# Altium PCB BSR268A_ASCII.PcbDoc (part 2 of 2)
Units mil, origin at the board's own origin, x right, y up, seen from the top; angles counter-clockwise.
Board outline 3689.1 x 2409.61 mil, 4 copper layers (Top Layer, Signal Layer 1, Signal Layer 2, Bottom Layer), stack 60.312 mil thick; 90 components, 29 nets, 160 pads, 335 vias.
Unrouted connection lines stored in the file: 5.
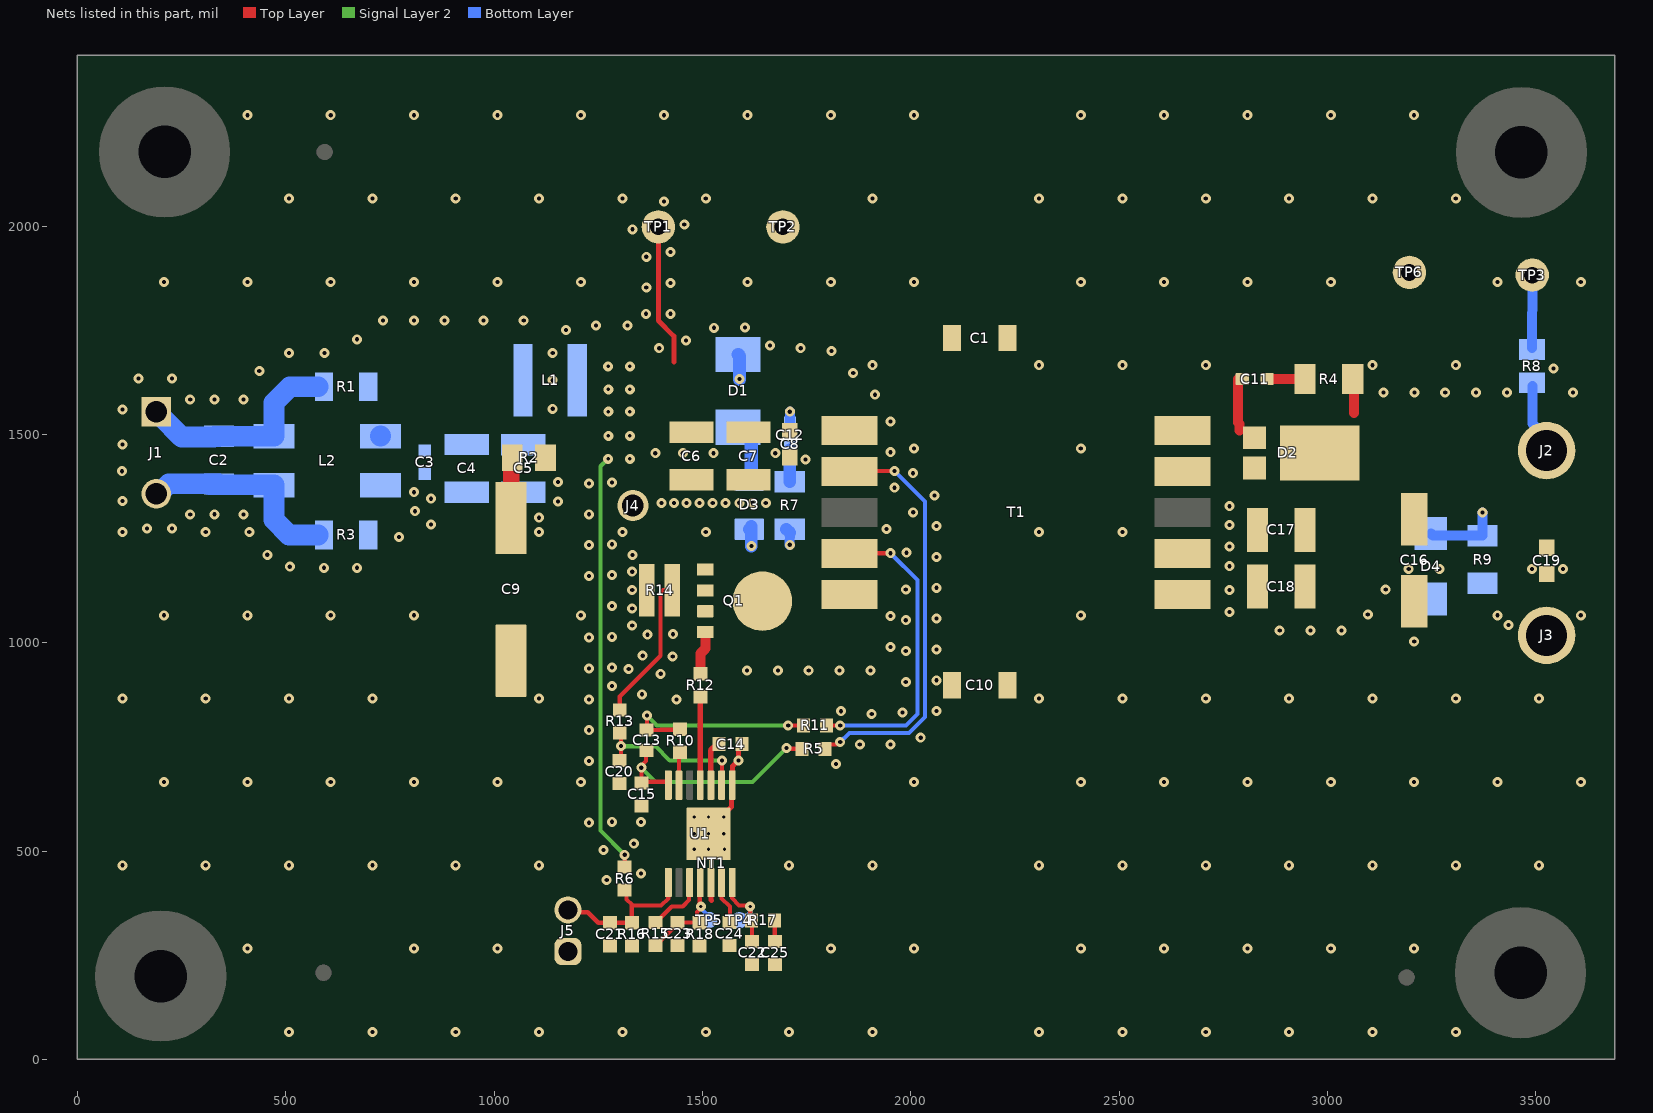
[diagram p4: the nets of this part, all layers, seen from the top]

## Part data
C1 C10: library part CMP-0008572-2, "CAP, CERM, 1000 pF, 2000 V, +/- 10%, X7R, 1206_190"
C2: library part CMP-0008881-2, "CAP, CERM, 0.1 uF, 100 V, +/- 10%, X7R, 1206"
C3 C8 C15 C19: library part CMP-0007469-4, "CAP, CERM, 0.1 uF, 100 V, +/- 10%, X7R, 0603"
C4 C5 C6 C7: library part CMP-0009134-2, "CAP, CERM, 4.7 uF, 100 V, +/- 10%, X7S, 1210"
C9: library part CMP-0095714-1, "Aluminum Electrolytic Capacitor 47uF 20% 80V 10.3x10.3x10.5mm SMT"
C11 C12: library part CMP-0096650-1, "0603 150 pF 100 V ±5 % Tolerance C0G/NP0 SMT Multilayer Ceramic Capacitor"
C13: library part CMP-0089170-1, "100pF ±10% 100V Ceramic Capacitor C0G, NP0 0603 (1608 Metric)"
C14: library part CMP-0064936-4, "CAP, CERM, 4.7 uF, 16 V,+/- 10%, X7R, 0603"
C16: library part CMP-0010711-1, "CAP, AL, 100 uF, 25 V, +/- 20%, 0.34 ohm, AEC-Q200 Grade 2, SMD"
C17 C18: library part CMP-0009224-2, "CAP, CERM, 22 uF, 25 V, +/- 10%, X7R, 1210"
C20: library part CMP-0007171-4, "CAP, CERM, 100 pF, 50 V, +/- 5%, C0G/NP0, 0603"
C21: library part CMP-0007131-4, "CAP, CERM, 1000 pF, 100 V, +/- 5%, C0G/NP0, AEC-Q200 Grade 1, 0603"
C22: library part CMP-0080062-1, "CAP, CERM, 47 pF, 50 V,+/- 5%, C0G/NP0, AEC-Q200 Grade 0, 0603"
C23 C24: library part CMP-0006857-4, "CAP, CERM, 0.1 uF, 16 V, +/- 5%, X7R, 0603"
C25: library part CMP-0006899-4, "CAP, CERM, 0.022 uF, 25 V, +/- 10%, X7R, 0603"
D1: library part CMP-0005655-4, "Diode, Zener, 28 V, 5 W, SMB"
D2: library part CMP-0077681-2, "Diode, Schottky, 100 V, 5 A, PowerDI5"
D3: library part CMP-0098302-1, "Diode 100 V 1A Surface Mount SOD-123H"
D4: library part CMP-0005526-4, "Diode, Zener, 18 V, 1 W, AEC-Q101, SMA"
FID1 FID2 FID3 FID4 FID5 FID6: library part CMP-0077181-1, "Fiducial mark.  There is nothing to buy or mount."
H1 H2 H3 H4: library part CMP-0003617-1, "Machine Screw, Round, #4-40 x 1/4, Nylon, Philips panhead"
H5 H6 H7 H8: library part CMP-0003610-1, "Standoff, Hex, 0.5\"L #4-40 Nylon"
J1: library part CMP-0054828-1, "Terminal Block, 5 mm, 2x1, Tin, TH"
J2 J3: library part CMP-0055121-1, "Terminal, Turret, TH, Triple"
J4: library part CMP-0055161-1
J5: library part CMP-0054794-2, "Header, 2.54 mm, 2x1, Gold, TH"
L1: library part CMP-0061651-2, "Inductor, Shielded, Composite, 22 uH, 3.4 A, 0.1 ohm, SMD"
L2: library part CMP-0085405-1, "Coupled inductor, 0.015 ohm, AEC-Q200 Grade 1, SMD"
Logo1: library part CMP-0074844-1
Logo2: library part CMP-0074838-1, "Texas Instrument Corporate Signature"
Logo3: library part CMP-0074847-1, "FCC_disclaimer"
Logo4: library part CMP-0074769-3
Logo5 Logo6: library part CMP-0074837-2, "IEC 61010-1 Hot Surface Warning"
Logo7 Logo8: library part CMP-0074835-1, "IEC 61010-1 High Voltage Warning"
NT1: library part CMP-0078142-6, "Single point connection between nets."
Q1: library part CMP-0032635-1, "N-Channel 100 V 8.4A (Ta), 31A (Tc) 3.6W (Ta), 49W (Tc) Surface Mount 5-DFN (5x6) (8-SOFL)"
R1 R3: library part CMP-0018748-3, "RES, 0, 5%, 0.25 W, AEC-Q200 Grade 0, 1206"
R2: library part CMP-0021914-2, "RES, 3.01, 1%, 0.125 W, 0805"
R4 R7: library part CMP-0017282-3, "RES, 100, 1%, 0.25 W, AEC-Q200 Grade 0, 1206"
R5: library part CMP-0022751-4, "RES, 10.0, 1%, 0.1 W, 0603"
R6: library part CMP-0022901-4, "RES, 200 k, 1%, 0.1 W, 0603"
R8: library part CMP-0020616-3, "RES, 0, 5%, 0.125 W, AEC-Q200 Grade 0, 0805"
R9: library part CMP-0017537-3, "RES, 3.24 k, 1%, 0.25 W, AEC-Q200 Grade 0, 1206"
R10: library part CMP-0022075-4, "RES, 165 k, 1%, 0.1 W, AEC-Q200 Grade 0, 0603"
R11: library part CMP-0025899-5, "RES, 1.0 k, 5%, 0.1 W, 0603"
R12: library part CMP-0025885-5, "RES, 0, 5%, 0.1 W, 0603"
R13: library part CMP-0022736-4, "RES, 100, 1%, 0.1 W, 0603"
R14: library part CMP-0015215-3, "RES, 0.02, 1%, 1 W, 0612"
R15: library part CMP-0022977-4, "RES, 294 k, 1%, 0.1 W, 0603"
R16: library part CMP-0022830-5, "RES, 16.9 k, 1%, 0.1 W, 0603"
R17: library part CMP-0022776-5, "RES, 12.1 k, 1%, 0.1 W, 0603"
R18: library part CMP-0022746-5, "RES, 10.0 k, 1%, 0.1 W, 0603"
T1: library part CMP-0097601-1, "EFD15 10PIN SMD FLYBACK TRANSFORMER"
TP1 TP3: library part CMP-0055137-2, "Test Point, Miniature, Red, TH"
TP2 TP6: library part CMP-0055138-2, "Test Point, Miniature, Black, TH"
TP4 TP5: library part CMP-0003825-1, "1mm Test Point, SMT"
U1: library part CMP-0091530-1, "120-VIN PSR Flyback Automotive DC/DC Controller With Low IQ and Low EMI, HTSSOP14"
ZZ1: library part CMP-0003616-3
ZZ2: library part CMP-0077236-1
ZZ3: library part CMP-0077237-1
ZZ4: library part CMP-0077238-1

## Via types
v1: diameter 24, hole 10, Top Layer to Bottom Layer, tented both sides, 314 vias
v2: diameter 24, hole 8, Top Layer to Bottom Layer, tented both sides, 12 vias
v3: diameter 20, hole 8, Top Layer to Bottom Layer, tented both sides, 9 vias

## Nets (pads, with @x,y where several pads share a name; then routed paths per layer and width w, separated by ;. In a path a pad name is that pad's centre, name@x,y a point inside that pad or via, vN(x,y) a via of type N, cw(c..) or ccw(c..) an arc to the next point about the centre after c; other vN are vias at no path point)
AGND: C21.2 C22.2 C23.1 C24.1 C25.2 J5.1 NT1.1 R16.1 R18.1 U1.5 | length 44.2
  Top Layer w12: R18.1@1486.8,278.49 R18.1@1487.78,278.49 ; U1.5@1520.49,424.41 1520.65,424.25 1520.65,383.23 1522.05,381.83
ISO-GND: C1.1 C10.1 C16.2 C17.1 C18.1 C19.2 D4.2 J3.1 R9.2 T1.9 T1.10 TP6.1
  other v1: 2308,66 2508,66 2708,66 2908,66 3108,66 3308,66 2408,266 2608,266 2808,266 3008,266 3208,266 2308,466 2508,466 2708,466 2908,466 3108,466 3308,466 3508,466 2408,666 2608,666 2808,666 3008,666 3208,666 3408,666 3608,666 2308,866 2508,866 2708,866 2908,866 3108,866 3308,866 3508,866 3208.17,1002.95 2885.33,1029.73 2959.33,1029.73 3033.33,1029.73 3434.55,1042.32 2408,1066 3408,1066 3608,1066 3096.74,1067.88 2765.26,1073.82 2765.26,1126.73 3139.81,1128.06 3194.98,1177.37 3268.98,1177.37 3490.98,1177.37 3564.98,1177.37 2765.26,1183.82 2765.26,1231.06 2308,1266 2508,1266 2765.26,1282.24 2765.26,1327.81 2408,1466 3134.55,1600.78 3208.55,1600.78 3282.55,1600.78 3356.55,1600.78 3430.55,1600.78 3588.92,1600.78 3542.52,1658.42 2308,1666 2508,1666 2708,1666 3108,1666 3308,1666 2408,1866 2608,1866 2808,1866 3008,1866 3408,1866 3608,1866 2308,2066 2508,2066 2708,2066 2908,2066 3108,2066 3308,2066 2408,2266 2608,2266 2808,2266 3008,2266 3208,2266
NetC2_2: C2.2 J1.2 L2.1 R3.1 | length 517.9
  Bottom Layer w50: J1.2@189.35,1357.28 195,1357.28 219.38,1381.66 C2.2@339.14,1381.66 ; C2.2@317.49,1379.96 339.67,1379.73 L2.1@471.56,1378.32 ; L2.1@471.56,1377.8 471.56,1295.3 508,1258.86 R3.1@577.91,1258.86
NetC3_1: C3.1 C4.1 C5.1 L1.1 L2.3 R1.2 | length 0.3
  Bottom Layer w50: L2.3@727.28,1496.1 L2.3@727.46,1495.91
NetC9_2: C9.2 R2.2 | length 136.2
  Top Layer w40: C9.2@1038.14,1310.26 1040.91,1313.04 1040.91,1441.36 R2.2@1043.68,1444.13
NetC11_1: C11.1 D2.1 D2.2 T1.6 T1.7 | length 124.8
  Top Layer w24: C11.1@2785.02,1632.87 2785.02,1528.24 2788.66,1524.61 2788.66,1509.54
NetC11_2: C11.2 R4.1 | length 85.3
  Top Layer w24: C11.2@2859.47,1632.87 R4.1@2944.75,1632.87
NetC12_1: C12.1 R7.2 | length 76.8
  Bottom Layer w30: R7.2@1709.68,1386.79 C12.1@1710.03,1463.6
NetC13_1: C13.1 R10.2 R11.1 | length 504.7
  Top Layer w10: v1(1366.64,825.43) 1366.64,791.52 1366.16,791.05 1400.35,791.05 1400.58,791.27 1445.25,791.27 R10.2@1446.36,792.38 ; v1@1702.13,801.52 R11.1@1742.3,801.52
  Signal Layer 2 w10: v1(1366.64,825.43) 1390.54,801.52 v1(1705.92,801.52)
NetC13_2: C13.2 C15.1 R5.1 U1.14 | length 584
  Top Layer w10: C13.2@1365.93,741.54 1364.57,740.18 1364.57,716.52 1356.01,707.96 1356.01,706.64 1354.79,705.42 1353.47,705.42 1353.47,664.11 C15.1@1353.84,663.73 1356.44,666.34 U1.14@1418.77,666.34 ; v1(1701.55,747.42) 1703.45,745.51 R5.1@1739.09,745.51
  Signal Layer 2 w10: v1@1353.33,699.7 1386.85,666.19 1620.32,666.19 v1(1701.55,747.42)
  other v1: 1353.33,700.18
NetC20_1: C20.1 R13.1 U1.9 | length 376.1
  Top Layer w10: C20.1@1300.65,717.54 1304.26,721.15 v1@1304.26,751.32 ; R13.1@1301.53,783.96 1304.23,781.26 v1(1304.23,752.36) v1@1304.76,751.83 ; U1.9@1546.72,666.34 v1(1546.72,717.52)
  Signal Layer 2 w10: v1@1304.76,751.83 1387.1,751.83 1421.41,717.52 v1(1546.72,717.52)
NetC21_1: C21.1 J5.2 R6.1 R16.2 U1.1 | length 385.3
  Top Layer w10: J5.2@1177.2,359.01 1182.89,353.32 1224.68,353.32 1249.91,328.09 C21.1@1277.82,328.09 R16.2@1330.51,328.09 1330.51,371.43 ; R6.1@1313.44,406.5 1317.72,402.22 1317.72,384.23 1330.51,371.43 ; U1.1@1418.13,424.41 1418.13,386.57 1400.65,369.09 1332.86,369.09 1330.51,371.43
NetC22_1: C22.1 R17.2 TP4.1 U1.7 | length 224
  Top Layer w10: U1.7@1571.67,424.41 1570.77,423.51 1570.77,387.15 1588.12,369.8 1611.95,369.8 v2(1614.63,367.13) 1614.63,336.53 R17.2@1617.55,333.61 1619.2,331.96 C22.1@1619.2,283.26
  Bottom Layer w10: TP4.1@1588.51,334.14 1596.46,334.14 1614.63,352.31 v2(1614.63,367.13)
NetC23_2: C23.2 R15.1 R18.2 TP5.1 U1.4 | length 282.3
  Top Layer w10: R15.1@1387.05,273.57 1388.04,273.57 1428.72,314.25 1428.72,317.94 1439.47,328.69 C23.2@1440.45,328.69 R18.2@1489.98,328.69 ; R18.2@1493.49,322.18 1491.03,326.76 R18.2@1489.98,328.69 ; R18.2@1493.49,328.09 1492.89,328.69 R18.2@1489.98,328.69 ; U1.4@1494.9,424.41 1493.25,422.76 1493.25,386.81 1493.49,386.57 1493.49,369.8 v2(1496.17,367.13) 1496.17,363.34 1486.8,353.96 1486.8,334.6 R18.2@1489.98,328.69
  Bottom Layer w10: v2(1496.17,367.13) 1498.85,364.45 1498.85,359.67 1516.1,342.42 TP5.1@1516.1,334.48
NetC24_2: C24.2 U1.6 | length 99
  Top Layer w10: U1.6@1546.08,424.41 1546.08,386.57 1565.79,366.85 C24.2@1565.79,333.61
NetC25_1: C25.1 R17.1 | length 50.8
  Top Layer w10: R17.1@1672.67,333.61 1673.65,332.63 C25.1@1673.65,283.26
NetD1_1: D1.1 D3.1 | length 94.4
  Bottom Layer w32: D3.1@1617.48,1390.34 D1.1@1617.48,1484.77
NetQ1_1: Q1.1 Q1.2 Q1.3 R13.2 R14.2 | length 352.5
  Top Layer w10: R13.2@1301.53,839.08 1301.53,870.74 1399.66,968.88 1399.66,1120.52 1405.52,1126.38 R14.2@1427.66,1126.38
NetQ1_4: Q1.4 R12.2 | length 92.6
  Top Layer w24: R12.2@1494.9,938.01 1494.9,973.75 1506.85,985.7 Q1.4@1506.85,1025.63
NetR8_2: R8.2 TP3.1 | length 174.9
  Bottom Layer w24: R8.2@3490.72,1707.47 TP3.1@3491.48,1882.37
NetR10_1: R10.1 U1.13 | length 67.8
  Top Layer w10: U1.13@1443.72,658.27 1443.72,725.88 R10.1@1443.87,726.04
NetR12_1: R12.1 U1.11 | length 211.8
  Top Layer w14: U1.11@1494.69,658.47 R12.1@1494.69,870.25
NetR15_2: R15.2 U1.3 | length 145.8
  Top Layer w10: R15.2@1387.05,328.69 1388.04,328.69 1426.48,367.13 1452.77,367.13 1468,382.36 1468,423.1 U1.3@1469.31,424.41
PGND: C1.2 C3.2 C4.2 C5.2 C6.2 C7.2 C8.2 C9.1 C10.2 C14.2 C15.2 C20.2 J4.1 L2.4 NT1.2 R3.2 R14.1 TP2.1 U1.8 U1.15 | length 269.9
  Top Layer w12: U1.15@1511.38,550.2 1514.84,553.66 U1.15@1522.96,553.66 ; v3(1514.58,541.34) 1514.58,545.28 v3(1551.32,582.02) ; U1.15@1547.26,577.97 1547.26,583.86 1569.4,606 1569.4,664.07 1571.99,666.66 1571.99,703.74 1585.77,717.52 v1(1586.91,717.52) 1586.91,744.92 C14.2@1598.88,756.89
  other v1: 508,66 708,66 908,66 1108,66 1308,66 1508,66 1708,66 1908,66 408,266 808,266 1008,266 1808,266 2008,266 1270.32,430.87 1352.61,445.87 108,466 308,466 508,466 708,466 908,466 1108,466 1708,466 1908,466 1262.28,502.98 1335.25,517.8 1227.4,568.24 1283.09,570.29 1352.75,569.88 208,666 408,666 608,666 808,666 1008,666 1208,666 2008,666 1820.21,709.17 1227.4,716.24 1877.66,755.8 1951.66,755.8 2023.81,772.23 1227.4,790.24 1906.21,829.36 1980.14,832.59 1832.49,835.83 2061.58,835.87 1227.4,864.24 1437.43,864.24 108,866 308,866 508,866 708,866 1108,866 1354.65,876.36 1283.09,896.2 1988.02,906.17 2061.58,909.87 1399.85,925.57 1607.04,933.57 1681.04,933.57 1755.04,933.57 1829.04,933.57 1903.04,933.76 1323.06,937.38 1227.4,938.24 1283.09,940.29 1428.72,966.67 1356.65,968.88 1988.02,980.17 2061.58,983.87 1951.07,990.05 1227.4,1012.24 1283.09,1014.29 1367.9,1019.41 1429.08,1020.5 1331.57,1041.38 1988.02,1054.17 2061.58,1057.87 1951.07,1064.05 208,1066 408,1066 608,1066 808,1066 1208,1066 1331.57,1082.5 1283.09,1088.29 1331.57,1126.38 1988.02,1128.17 2061.58,1131.87 1227.4,1160.24 1283.09,1162.29 1331.57,1170.5 591.74,1179.89 670.95,1179.89 509.73,1182.5 2061.58,1205.87 455.81,1211.12 1332.15,1210.59 1989.59,1216.13 1227.4,1234.24 1283.09,1236.29 772.18,1254.02 108,1266 308,1266 412.5,1266 1108,1266 1308,1266 1508,1266 1941.98,1272.77 167.26,1274.61 227.24,1274.61 2061.58,1279.87 848.9,1283.53 1108.13,1300.13 270.76,1307.92 328.68,1308.24 398.34,1307.92 1227.4,1308.24 2005.9,1313.07 809.91,1315.79 1402.03,1335.23 1431.6,1335.23 1461.75,1335.23 1493.25,1335.23 1524.71,1335.23 1555.66,1335.23 1652,1335.23 1588.37,1335.95 1620.53,1335.95 1153.47,1339.07 108,1339.95 848.9,1345.69 2056.8,1353.71 808,1361.38 1961.3,1372.13 1227.4,1382.24 1283.09,1384.29 1153.47,1385.46 2005.31,1406.87 106.67,1411.69 1747.27,1439.56 1386.85,1455.01 1452.9,1455.01 1526.9,1455.01 1674.9,1455.01 1951.07,1457.21 2008,1466 108,1475.67 1951.07,1531.21 108,1559.89 1140.73,1561.51 270.76,1583.69 328.68,1583.69 398.34,1583.69 1914.22,1595.38 1140.73,1630.1 146.28,1633.89 227.24,1633.89 1861.9,1647.7 436.61,1652.59 1908,1666 508,1695.77 593.33,1695.77 1140.73,1695.77 1809.57,1700.03 1396.2,1706.81 1735.88,1706.81 1662.2,1713.65 1460.42,1725.65 670.95,1728.37 1172.78,1750.8 1527.97,1755.87 1601.96,1756.63 1244.43,1761.65 1320.23,1761.65 881.37,1773.19 1071.17,1773.19 733.68,1773.66 807.68,1773.66 974.54,1773.66 1364.85,1789.58 1423.14,1789.58 1365.29,1852.26 1423.14,1863.58 208,1866 408,1866 608,1866 808,1866 1008,1866 1208,1866 1608,1866 1808,1866 2008,1866 1365.29,1926.26 1423.14,1937.58 1331.99,1992.35 1456.44,2003.66 1407.59,2059.24 508,2066 708,2066 908,2066 1108,2066 1308,2066 1508,2066 1908,2066 408,2266 608,2266 808,2266 1008,2266 1208,2266 1408,2266 1608,2266 1808,2266 2008,2266
  other v3: 1480.72,504.16 1514.58,504.16 1553,504.16 1480.72,541.34 1551.51,541.34 1480.46,581.66 1514.59,581.66
SW: D3.2 Q1.5-6 R7.1 R11.2 T1.1 T1.2 | length 835.1
  Top Layer w10: R11.2@1797.42,801.52 v1(1830.71,801.52) ; T1.2@1852.77,1214.26 1853.41,1214.91 v1(1951.44,1214.91)
  Bottom Layer w10: v1(1830.71,801.52) 1988.44,801.52 2015.87,828.94 2015.87,1150.48 v1(1951.44,1214.91)
  Bottom Layer w24: v1@1709.48,1235.22 R7.1@1709.68,1264.44
  Bottom Layer w30: D3.2@1612.48,1272.23 1612.67,1272.43 D3.2@1617.48,1272.43 ; v1(1617.48,1232.02) D3.2@1617.48,1272.43 ; D3.2@1617.48,1280.11 D3.2@1617.48,1272.43 ; R7.1@1701.7,1272.43 R7.1@1709.68,1264.44
  other v1: 1709.68,1235.22
VCC: C14.1 U1.10 | length 98.3
  Top Layer w14: U1.10@1521.13,666.34 1519.84,667.62 1519.84,741.83 1534.91,756.89 C14.1@1535.89,756.89
VIN: C6.1 C7.1 C8.1 C12.2 D1.2 L1.2 R2.1 R5.2 R6.2 T1.4 T1.5 TP1.1 | length 2438.6
  Top Layer w10: R6.2@1313.44,461.61 1313.44,491.09 v1(1313.49,491.14) ; R5.2@1794.21,745.51 1804.26,755.56 1820.7,755.56 1826.92,761.78 v1(1830.71,761.78) ; T1.4@1852.77,1411.11 1853.48,1411.83 v1(1960.98,1411.83)
  Top Layer w12: TP1.1@1394.22,1998.03 1394.22,1773.19 1431.49,1735.91 1431.49,1673.59
  Signal Layer 2 w10: v2@1273.14,1441.46 1255.24,1423.56 1255.24,549.39 v1(1313.49,491.14)
  Bottom Layer w10: v1(1830.71,761.78) 1852.58,783.64 1995.85,783.64 2033.74,821.54 2033.74,1339.07 v1(1960.98,1411.83)
  Bottom Layer w24: v1(1709.68,1554.6) C12.2@1709.93,1527.58
  Bottom Layer w32: D1.2@1585.77,1691.7 1589.09,1688.38 v1(1589.09,1632.75)
  other v2: 1273.94,1441.46 1325.94,1441.46 1274.13,1496.76 1325.94,1496.76 1274.13,1554.78 1325.94,1554.78 1274.13,1608.1 1325.94,1608.1 1273.94,1663.36 1325.76,1663.36
VIN_EMI: C2.1 J1.1 L2.2 R1.1 | length 529.8
  Bottom Layer w50: J1.1@190.23,1553.25 199.79,1543.7 200.67,1543.7 250.29,1494.08 327.64,1494.08 328.26,1494.7 C2.1@338.46,1494.7 ; C2.1@317.08,1494.55 328.21,1494.65 334.69,1494.7 339.69,1494.75 L2.2@471.56,1495.91 471.56,1576.03 509.73,1614.21 R1.1@577.91,1614.21
VOUT: C16.1 C17.2 C18.2 C19.1 D2.3 D4.1 J2.1 R4.2 R8.1 R9.1 | length 435.1
  Top Layer w24: 3063.56,1551.29 R4.2@3063.56,1634.74
  Bottom Layer w24: D4.1@3248.03,1262.56 3253.7,1256.89 R9.1@3372.22,1256.89 v1(3372.22,1312.69) ; R8.1@3491.48,1616.14 3491.48,1526.44 3525.97,1491.94 J2.1@3525.97,1461.15
pads on no net: FID1.1 FID2.1 FID3.1 FID4.1 FID5.1 FID6.1 H1.1 H2.1 H3.1 H4.1 H5.0 H6.0 H7.0 H8.0 T1.3 T1.8 U1.2 U1.12

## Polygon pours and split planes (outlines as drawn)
AGND on Top Layer "TOP_LAYER_AGND_P230" (solid, remove dead copper, pour order 230): 1513.33,398.44 1513.33,316.05 1165.61,316.05 1135.39,285.84 1135.39,233.09 1162.78,205.71 1703.37,205.71 1703.37,316.05 1538.17,316.05 1538.17,398.44
PGND on Top Layer "TOP_LAYER_PGND_P235" (solid, remove dead copper, pour order 235): -2.08,-7.36 2123.91,-7.36 2123.91,2402.25 -2.08,2402.25
SW on Top Layer "TOP_LAYER_SW_P231" (solid, remove dead copper, pour order 231): 1928.64,1254.39 1928.64,982.58 1910.2,964.14 1565.95,964.14 1547.79,982.3 1547.79,1249.02 1567.07,1268.3 1914.73,1268.3
ISO-GND on Top Layer "TOP_LAYER_ISO-GND_P234" (solid, remove dead copper, pour order 234): 2208.77,0 2208.77,2409.61 3689.1,2409.61 3689.1,0
VOUT on Top Layer "TOP_LAYER_VOUT_P233" (solid, remove dead copper, pour order 233): 2873.66,1578.35 2873.66,1199.8 2873.66,1052.17 3074.31,1052.17 3074.31,1094.29 3179.82,1199.8 3689.1,1199.8 3689.1,1578.35
NetQ1_1 on Top Layer "TOP_LAYER_NETQ1_1_P228" (solid, remove dead copper, pour order 228): 1531.62,1054.38 1531,1053.76 1408.66,1053.76 1408.66,1209.42 1403.94,1214.13 1531.97,1214.13
NetC11_1 on Top Layer "TOP_LAYER_NETC11_1_P229" (solid, remove dead copper, pour order 229): 2575.56,1373.27 2575.56,1547.39 2856.88,1547.39 2856.88,1373.03
VIN on Top Layer "TOP_LAYER_VIN_P232" (solid, remove dead copper, pour order 232): 1928.64,1367.13 1769.7,1367.13 1769.7,1461.51 1753.77,1477.44 1350.74,1477.44 1350.74,1410.83 1082.68,1410.83 1082.68,1518.29 1172.78,1518.29 1172.78,1684.38 1793.5,1684.38 1928.64,1549.23
NetC3_1 on Bottom Layer "BOTTOM_LAYER_NETC3_1_P244" (solid, remove dead copper, pour order 244): 1133.01,1513.01 1133.01,1445.66 943.27,1445.66 797.16,1445.66 782.31,1460.51 670.95,1460.51 670.95,1651.99 747.1,1728.14 1098.77,1728.14 1098.77,1547.25
SW on Bottom Layer "BOTTOM_LAYER_SW_P242" (solid, remove dead copper, pour order 242): 1569.4,1179.89 1689.92,1179.89 1689.92,1021.38 1569.95,1021.38
ISO-GND on Bottom Layer "BOTTOM_LAYER_ISO-GND_P245" (solid, remove dead copper, pour order 245): 2208.77,0 2208.77,2409.61 3689.1,2409.61 3689.1,0
PGND on Bottom Layer "BOTTOM_LAYER_PGND_P246" (solid, remove dead copper, pour order 246): -1.15,4.39 2124.83,4.39 2124.83,2414 -1.15,2414
VIN on Bottom Layer "BOTTOM_LAYER_VIN_P243" (solid, remove dead copper, pour order 243): 1177.68,1407.89 1176.18,1409.39 1176.18,1728.37 1365.32,1728.37 1365.32,1407.89
SW on Signal Layer 1 "SIGNAL_LAYER_1_SW_P236" (solid, remove dead copper, pour order 236): 1569.4,1179.77 1689.92,1179.77 1689.92,1021.5 1569.95,1021.5
PGND on Signal Layer 1 "SIGNAL_LAYER_1_PGND_P238" (solid, remove dead copper, pour order 238): 0,0 2125.98,0 2125.98,2409.61 0,2409.61
ISO-GND on Signal Layer 1 "SIGNAL_LAYER_1_ISO-GND_P237" (solid, remove dead copper, pour order 237): 2208.77,0 3689.1,0 3689.1,2409.61 2208.77,2409.61
SW on Signal Layer 2 "SIGNAL_LAYER_2_SW_P239" (solid, remove dead copper, pour order 239): 1569.15,1252.92 1926.88,1252.92 1926.88,987.2 1570.07,987.2
PGND on Signal Layer 2 "SIGNAL_LAYER_2_PGND_P241" (solid, remove dead copper, pour order 241): 0,0 2125.98,0 2125.98,2409.61 0,2409.61
ISO-GND on Signal Layer 2 "SIGNAL_LAYER_2_ISO-GND_P240" (solid, remove dead copper, pour order 240): 2208.77,0 3689.1,0 3689.1,2409.61 2208.77,2409.61

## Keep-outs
Keep-Out Layer:
  the board outline again, w10
  text ".Layer_Name" at 577,-858.49 h60

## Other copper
Top Layer:
  text ".Layer_Name" at 577,-858.49 h60
Signal Layer 1:
  text ".Layer_Name" at 580.71,-856.3 h60
Signal Layer 2:
  text ".Layer_Name" at 580.71,-856.3 h60
Bottom Layer:
  text ".Layer_Name" at 577,-858.49 h60

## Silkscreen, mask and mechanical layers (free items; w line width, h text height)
Top Overlay:
  text "VIN SNS+" at 1196.94,1872 h35
  text "VIN SNS-" at 1631.15,1872 h35
  text "VOUT SNS-" at 2979.99,1766.13 h35
  text "VOUT SNS+" at 3348.03,1766.13 h35
  text "VIN+" at 156.28,1701.93 h60
  text "16VDC 1A MAX" at 3302.75,1683.4 h30
  text "VOUT+" at 3379.75,1588.35 h60
  text "PGND" at 1280.13,1245.59 h35
  text "VIN-" at 156.05,1142.89 h60
  text "VOUT-" at 3369.36,846.61 h60
  text "LM5185EVM-SIO" at 2415.1,440.87 h60
  text "EN" at 1044.14,344.05 h35
  text "'.PRJ_Number'.PCB_Rev" at 2408.01,307.04 h108.27
  text "AGND" at 980.41,235.54 h35
  text ".Layer_Name" at 577,-858.49 h60
Bottom Overlay:
  text ".Layer_Name" at 577,-858.49 h60
Top Paste:
  text ".Layer_Name" at 577,-858.49 h60
Bottom Paste:
  text ".Layer_Name" at 577,-858.49 h60
Top Solder:
  text ".Layer_Name" at 577,-858.49 h60
  text ".Layer_Name" at 577,-858.49 h60
Bottom Solder:
  text ".Layer_Name" at 577,-858.49 h60
Drill Guide:
  text ".Layer_Name" at 577,-858.49 h60
M1 Board Outline:
  the board outline again, w10
  text ".Layer_Name" at 577,-858.49 h60
M2 Board Dimensions:
  rectangle: 0,-275 125,-150
  rectangle: 125,-400 500,-275
  lines w7: 0,-275 1000,-275 ; 125,-400 125,-150 ; 250,-400 250,-150 ; 500,-400 500,-150 ; 750,-400 750,-150 ; 0,-400 1000,-400 1000,-150 0,-150 0,-400
  text ".Layer_Name" at 577,-858.49 h60
M3 3D STEP Top:
  text ".Layer_Name" at 577,-858.49 h60
M4 3D STEP Bottom:
  text ".Layer_Name" at 577,-858.49 h60
M5 Assembly Top:
  lines w10: -292,-930.17 6308,-930.17 ; -292,-726.83 6310,-726.83 ; -292,-523.5 -292,-1133.5 3713,-1133.5 6310,-1133.5 6310,-523.5 -291.5,-523.5 -291.5,-1133.5 1284,-1133.5 ; 2173,-1133.5 2173,-523.5 ; 3440,-726.83 3440,-523.5 ; 4280,-726.83 4280,-523.5 ; 4902,-1140 4902,-937.17
  text "COMPONENTS MARKED 'DNP' SHOULD NOT BE POPULATED." at 1153.5,-318.5 h60
  text "ASSEMBLY VARIANT:" at 1153,-434 h60
  text ".VariantName" at 2189,-434 h60
  text "PCB VIEWED FROM TOP SIDE" at -228.5,-655.67 h60
  text "BOARD #:" at 2248,-655.67 h60
  text ".PRJ_Number" at 2793.5,-655.67 h60
  text "REV:" at 3638,-655.67 h60
  text ".PCB_Rev" at 3929.5,-655.67 h60
  text "SVN REV:" at 4476,-655.67 h60
  text ".VersionControl_RevNumber" at 4982,-655.67 h60
  text "TID #:" at 2248,-859 h60
  text ".TID" at 2793.5,-859 h60
  text "PLOT NAME =" at -228.5,-1064.34 h60
  text ".plot_File_Name" at 577,-1064.34 h60
  text "GENERATED    :" at 2250,-1064.34 h60
  text ".Print_Date" at 3119.5,-1064.34 h60
  text ".Print_Time" at 3848.5,-1064.34 h60
  text "TEXAS INSTRUMENTS" at 5113,-1064.34 h60
M6 Assembly Bottom:
  lines w10: -292.5,-727.33 6309.5,-727.33 ; -290.5,-930.67 6309.5,-930.67 ; 1115.5,-1140.5 1115.5,-937.67 ; 1737.5,-727.33 1737.5,-524 ; 2577.5,-727.33 2577.5,-524 ; 3844.5,-1134 3844.5,-524 ; 4733.5,-1134 6309,-1134 6309,-524 -292.5,-524 -292.5,-1134 2304.5,-1134 6309.5,-1134 6309.5,-524
  text "COMPONENTS MARKED 'DNP' SHOULD NOT BE POPULATED." at 6102,-318 h60
  text ".VariantName" at 5058,-434 h60
  text "ASSEMBLY VARIANT:" at 6097,-434 h60
  text ".VersionControl_RevNumber" at 1035.5,-656.17 h60
  text "SVN REV:" at 1541.5,-656.17 h60
  text ".PCB_Rev" at 2088,-656.17 h60
  text "REV:" at 2379.5,-656.17 h60
  text ".PRJ_Number" at 3224,-656.17 h60
  text "BOARD #:" at 3769.5,-656.17 h60
  text "PCB VIEWED FROM BOTTOM SIDE" at 6246,-656.17 h60
  text ".TID" at 3224,-859.5 h60
  text "TID #:" at 3769.5,-859.5 h60
  text "TEXAS INSTRUMENTS" at 904.5,-1064.84 h60
  text ".Print_Time" at 2169,-1064.84 h60
  text ".Print_Date" at 2898,-1064.84 h60
  text "GENERATED    :" at 3767.5,-1064.84 h60
  text ".plot_File_Name" at 5440.5,-1064.84 h60
  text "PLOT NAME =" at 6246,-1064.84 h60
M9 Title Sheet:
  lines w10: -491.5,1041.5 -291.5,1041.5 ; -491.5,3416.5 -291.5,3416.5 ; -491.5,5791.5 -291.5,5791.5 ; 2008.5,-1333.5 2008.5,-1133.5 ; 2008.5,7966.5 2008.5,8166.5 ; 4508.5,-1333.5 4508.5,-1133.5 ; 4508.5,7966.5 4508.5,8166.5 ; 6321,-1133.5 6321,-523.5 11303.5,-523.5 ; 7008.5,-1333.5 7008.5,-1133.5 ; 7008.5,7966.5 7008.5,8166.5 ; 9508.5,-1333.5 9508.5,-1133.5 ; 9508.5,7966.5 9508.5,8166.5 ; 11303.5,-1133.5 11303.5,-523.5 ; 11303.5,-823.5 14303.5,-823.5 ; 11303.5,-223.5 14303.5,-223.5 ; 11304.5,370.5 14304.5,370.5 ; 12008.5,-1333.5 12008.5,-1133.5 ; 12008.5,7966.5 12008.5,8166.5 ; 12808.5,-1123.5 12808.5,-523.5 ; 14303.5,-523.5 11303.5,-523.5 ; 14303.5,76.5 11303.5,76.5 ; 14308.5,66.5 14308.5,-1133.5 ; 14308.5,871 11304.5,871 11303.5,871 11303.5,370.5 11303.5,76.5 ; 14308.5,1041.5 14508.5,1041.5 ; 14308.5,3416.5 14508.5,3416.5 ; 14308.5,5791.5 14508.5,5791.5 ; 11303.5,-523.5 11303.5,76.5 ; 14308.5,-1133.5 14308.5,7966.5 -291.5,7966.5 -291.5,-1133.5 14308.5,-1133.5 ; -491.5,-1333.5 -491.5,8166.5 14508.5,8166.5 14508.5,-1333.5 -491.5,-1333.5
  text "1" at 739.84,8036.5 h70
  text "2" at 3235.5,8036.5 h70
  text "3" at 5724.84,8036.5 h70
  text "4" at 8231.51,8036.5 h70
  text "5" at 10730.5,8036.5 h70
  text "6" at 13235.5,8036.5 h70
  text "A" at -416.5,6893.5 h70
  text "A" at 14383.5,6893.5 h70
  text "B" at -416.5,4513.5 h70
  text "B" at 14383.5,4513.5 h70
  text "C" at -416.5,2138.5 h70
  text "C" at 14383.5,2138.5 h70
  text "PROJECT TITLE:" at 11343.5,277.5 h45
  text ".PRJ_Title" at 11393.5,144.17 h70
  text "DESIGNED FOR:" at 11343.5,-23.5 h45
  text ".PRJ_Customer" at 11393.5,-163.5 h70
  text "D" at -416.5,-231.5 h70
  text "D" at 14383.5,-231.5 h70
  text "FILE NAME:" at 11343.5,-323.5 h45
  text ".PCB_File_Name_No_Path" at 11393.5,-443.5 h70
  text "Texas Instruments (TI) and/or its licensors do not warrant the accuracy or completeness of this specification" at 6374,-605.34 h45
  text "ENGINEER:" at 11343.5,-613.5 h45
  text "LAYOUT BY:" at 12848.5,-613.5 h45
  text "or any information contained therein. TI and/or its licensors do not warrant that this design will meet" at 6329.01,-718 h45
  text ".PRJ_Engineer" at 11393.5,-768.49 h70
  text ".PCB_Layout" at 12899,-768.49 h70
  text "the specifications, will be suitable for your application or fit for any particular purpose, or will operate in" at 6329.01,-830.67 h45
  text ".Layer_Name" at 577,-858.49 h60
  text "ALTIUM DESIGNER VERSION:" at 12848.5,-923.5 h45
  text "an implementation. TI and/or its licensors do not warrant that the design is production worthy. You should" at 6329.01,-943.33 h45
  text "completely validate and test your design implementation to confirm the system functionality for your application." at 6374,-1056 h45
  text ".print_Scale" at 11393.5,-1056.83 h70
  text ".Application_BuildNumber" at 12899,-1056.83 h70
  text "1" at 739.84,-1263.5 h70
  text "2" at 3235.5,-1263.5 h70
  text "3" at 5724.84,-1263.5 h70
  text "4" at 8231.51,-1263.5 h70
  text "5" at 10730.5,-1263.5 h70
  text "6" at 13235.5,-1263.5 h70
M10 Fab Notes:
  drawing of 189 lines, arcs and shapes, not listed
  text "DESIGN INFORMATION" at 12382.02,6356.17 h60
  text "MIN. TRACK WIDTH:" at 11737.46,6224.05 h60
  text "10" at 12833.7,6224.05 h60
  text "MIL" at 12988.46,6224.05 h60
  text "7.874" at 12667.32,6102.36 h60
  text "MIN. CLEARANCE:" at 11737.46,6099.92 h60
  text "MIL" at 12988.46,6099.92 h60
  text "20" at 12834.65,5984.25 h60
  text "MIN. VIA PAD SIZE:" at 11737.46,5975.8 h60
  text "MIL" at 12988.46,5975.8 h60
  text "0.05mm (2MIL)" at 12432.46,5845.9 h60
  text "MINIMUM ANNULAR RING" at 11408.23,5837.67 h60
  text "EXTERNAL" at 13140.46,5837.67 h60
  text "PER" at 11608.23,5727.55 h60
  text "IPC-D-275 CLASS 2 LEVEL C" at 11828.23,5727.54 h60
  text "MIL, HOLES" at 13316.46,5627.07 h60
  text "+/-" at 12924,5618.48 h60
  text "+/-" at 13778,5618.48 h60
  text "REGISTRATION TOLERANCES:" at 11408.23,5617.42 h60
  text "METAL" at 12608,5617.42 h60
  text "5" at 13184.2,5617.42 h60
  text "3" at 14017.2,5617.42 h60
  text "MIL" at 14133.46,5617.42 h60
  text "HOLE SIZE TOLERANCE (UNLESS OTHERWISE SPECIFIED):" at 11408.23,5519.1 h60
  text "+/-" at 13778,5516.23 h60
  text "3" at 14017.2,5515.17 h60
  text "MIL" at 14133.46,5515.17 h60
  text "MATERIAL:" at 11333.46,5377.52 h60
  text "FR-4 High Tg" at 12319.9,5249 h60
  text "X" at 12175.46,5241.01 h60
  text "FR-408" at 11754.46,5236.49 h60
  text "OTHER" at 13242.46,5236.49 h60
  text "62 MIL (1.6mm) +/-10%" at 12074.56,5093.46 h60
  text "X" at 11954.46,5091.01 h60
  text "THICKNESS:" at 11408.23,5085.24 h60
  text "OTHER" at 13359.46,5085.24 h60
  text "TOLERANCE:" at 11408.23,4946.92 h60
  text "X" at 12256.46,4946.92 h60
  text "ANSI IPC-6012 TYPE 3 CLASS 2" at 12434.48,4946.92 h60
  text "OTHER +/-" at 12434.46,4802.73 h60
  text "BOW & TWIST:" at 11408.23,4657.54 h60
  text "X" at 12256.46,4657.54 h60
  text "ANSI IPC-6012 TYPE 3 CLASS 2" at 12434.48,4657.54 h60
  text "OTHER +/-" at 12434.46,4510.85 h60
  text "DRILLING:" at 11333.46,4380.23 h60
  text "NC_DRILL FILES" at 13094.46,4275.04 h60
  text "REFERENCE:" at 11408.23,4271.1 h60
  text "X" at 12065.46,4271.01 h60
  text "AS SHOWN" at 12243.46,4271.1 h60
  text "X" at 12966.46,4271.1 h60
  text "OTHER" at 13392.46,4128.85 h60
  text "PTH COPPER THICKNESS:" at 11407.91,4125.32 h60
  text "X" at 12547.14,4125.32 h60
  text "20-30 um" at 12675.14,4125.32 h60
  text "BOARD FINISH:" at 11333.46,3977.73 h60
  text "SILKSCREEN:" at 11488.68,3867.6 h60
  text "X" at 12446.46,3867.6 h60
  text "TOP" at 12563.46,3867.6 h60
  text "X" at 12956.46,3867.6 h60
  text "BOTTOM" at 13074.46,3867.6 h60
  text "SILKSCREEN COLOR:" at 11488.68,3712.41 h60
  text "X" at 12445.46,3712.41 h60
  text "WHITE" at 12563.46,3712.41 h60
  text "OTHER" at 13074.46,3712.41 h60
  text "X" at 12576.46,3568.96 h60
  text "GREEN" at 12694.46,3568.96 h60
  text "OTHER" at 13312.46,3568.96 h60
  text "SOLDER RESIST COLOR:" at 11488.68,3562.1 h60
  text "X" at 12576.46,3414.71 h60
  text "MATTE" at 12694.46,3414.71 h60
  text "SEMI-GLOSS" at 13312,3414.07 h60
  text "IMMERSION GOLD (ENIG)" at 12394.46,3241.94 h60
  text "ENEPIG" at 13732,3234.72 h60
  text "SURFACE FINISH:" at 11333.46,3233.72 h60
  text "X" at 12216.46,3233.72 h60
  text "IMM. TIN/SILVER OR EQUIV" at 11663,3096.4 h60
  text "OTHER" at 13094.46,3092.47 h60
  text "ARRAY/PANEL:" at 11333.46,2937.09 h60
  text "CUT AND TRIM PER M1 BOARD OUTLINE" at 12394.46,2928.87 h60
  text "N.C. ROUTE" at 12394.46,2792.9 h60
  text "X" at 13082.46,2792.9 h60
  text "V. SCORE" at 13260.46,2792.9 h60
  text "CERTIFICATION:" at 11333.46,2663.77 h60
  text "MATERIALS AND WORKMANSHIP FOR ALL PCBS" at 12058.46,2663.77 h60
  text "TO MEET OR EXCEED THE REQUIREMENTS OF:" at 12058.46,2569.71 h60
  text "X" at 11695.97,2441.08 h60
  text "ANSI IPC-A-600F CLASS ->" at 11823.96,2441.08 h60
  text "X" at 13471.97,2441.08 h60
  text "2" at 13581.96,2441.08 h60
  text "1" at 13266.96,2439.58 h60
  text "3" at 13935.96,2439.58 h60
  text "X" at 12507.97,2293.39 h60
  text "RoHS" at 12635.96,2293.39 h60
  text "OTHER" at 13280.36,2293.39 h60
  text "PER ORDER" at 13677.42,2293.39 h60
  text "ALL BOARDS MUST MEET OR EXCEED UL94-V0 REQUIREMENTS." at 11361,2139.57 h60
  text "PCB MUST BEAR THE UL94V-0 UL REGISTERED MATERIAL ID NUMBER" at 11361,2023.5 h60
  text "ADDITIONAL REQUIREMENTS:" at 11333.46,1854.08 h60
  text "MICROSECTION:" at 11408.23,1746.95 h60
  text "YES" at 12313.96,1746.95 h60
  text "REQUIRED" at 13175.46,1602.62 h60
  text "BARE BOARD ELEC. TEST:" at 11408.23,1599.76 h60
  text "NONE" at 12713.96,1599.76 h60
  text "X" at 13057.46,1599.76 h60
  text "PER ORDER" at 13767.46,1599.76 h60
  text "XX MIL VIAS REQUIRE NON-CONDUCTIVE FILL AND PLANARIZE" at 11576.38,1394.82 h59
  text "XX MIL VIAS REQUIRE CONDUCTIVE FILL AND PLANARIZE" at 11584.38,1290.84 h60
  text "OUTER XX MIL TRACES REQUIRE 50 OHM SINGLE-ENDED IMPEDANCE" at 11583.39,1127.46 h58
  text "LAYER 2 & 3 (INNER LAYERS) XX MIL WIDE, XX MIL SPACE / TRACES REQUIRE 100 OHM DIFFERENTIAL IMPEDANCE" at 11575.39,891.74 h60
  text ".Layer_Name" at 577,-858.49 h60
M11 Gerber Information:
  lines w10: -292,-930.17 6308,-930.17 ; -292,-726.83 6310,-726.83 ; -292,-523.5 -292,-1133.5 3713,-1133.5 6310,-1133.5 6310,-523.5 -291.5,-523.5 -291.5,-1133.5 1284,-1133.5 ; 2173,-1133.5 2173,-523.5 ; 3440,-726.83 3440,-523.5 ; 4280,-726.83 4280,-523.5 ; 4902,-1140 4902,-937.17
  text "ALL ARTWORK VIEWED FROM TOP SIDE" at -228.5,-655.67 h60
  text "BOARD #:" at 2248,-655.67 h60
  text ".PRJ_Number" at 2793.5,-655.67 h60
  text "REV:" at 3638,-655.67 h60
  text ".PCB_Rev" at 3929.5,-655.67 h60
  text "SVN REV:" at 4476,-655.67 h60
  text ".VersionControl_RevNumber" at 4982,-655.67 h60
  text "LAYER NAME =" at -228.5,-858.49 h60
  text "TID #:" at 2248,-859 h60
  text ".TID" at 2793.5,-859 h60
  text "PLOT NAME =" at -228.5,-1064.34 h60
  text ".plot_File_Name" at 577,-1064.34 h60
  text "GENERATED    :" at 2250,-1064.34 h60
  text ".Print_Date" at 3119.5,-1064.34 h60
  text ".Print_Time" at 3848.5,-1064.34 h60
  text "TEXAS INSTRUMENTS" at 5113,-1064.34 h60
M12 Stackup:
  drawing of 295 lines, arcs and shapes, not listed
  text "Layer" at 9821.59,7874.94 h60
  text "Name" at 10231.51,7874.94 h60
  text "Material" at 11171.25,7874.94 h60
  text "Thickness" at 12031.02,7874.94 h60
  text "Constant" at 12680.85,7874.94 h60
  text "Board Layer Stack" at 13250.71,7874.94 h60
  text "Top Overlay" at 10231.51,7754.94 h60
  text "Top Solder" at 10231.51,7634.94 h60
  text "Solder Resist" at 11171.25,7634.94 h60
  text "0.40mil" at 12031.02,7634.94 h60
  text "3.5" at 12680.85,7634.94 h60
  text "1" at 9821.59,7514.94 h60
  text "Top Layer" at 10231.51,7514.94 h60
  text "CF-005" at 11171.25,7514.94 h60
  text "2.76mil" at 12031.02,7514.94 h60
  text "Dielectric 1" at 10231.51,7394.94 h60
  text "FR-4 High Tg" at 11171.25,7394.94 h60
  text "8.00mil" at 12031.02,7394.94 h60
  text "4.1" at 12680.85,7394.94 h60
  text "2" at 9821.59,7274.94 h60
  text "Signal Layer 1" at 10231.51,7274.94 h60
  text "CF-004" at 11171.25,7274.94 h60
  text "1.40mil" at 12031.02,7274.94 h60
  text "Dielectric1" at 10231.51,7154.94 h60
  text "FR-4 High Tg" at 11171.25,7154.94 h60
  text "36.00mil" at 12031.02,7154.94 h60
  text "4.8" at 12680.85,7154.94 h60
  text "3" at 9821.59,7034.94 h60
  text "Signal Layer 2" at 10231.51,7034.94 h60
  text "CF-004" at 11171.25,7034.94 h60
  text "1.40mil" at 12031.02,7034.94 h60
  text "Dielectric 2" at 10231.51,6914.94 h60
  text "FR-4 High Tg" at 11171.25,6914.94 h60
  text "8.00mil" at 12031.02,6914.94 h60
  text "4.1" at 12680.85,6914.94 h60
  text "4" at 9821.59,6794.94 h60
  text "Bottom Layer" at 10231.51,6794.94 h60
  text "CF-005" at 11171.25,6794.94 h60
  text "2.76mil" at 12031.02,6794.94 h60
  text "Bottom Solder" at 10231.51,6674.94 h60
  text "Solder Resist" at 11171.25,6674.94 h60
  text "0.40mil" at 12031.02,6674.94 h60
  text "3.5" at 12680.85,6674.94 h60
  text "Bottom Overlay" at 10231.51,6554.94 h60
  text "Total board thickness:" at 9821.59,6434.94 h60
  text "61.11mil" at 12031.02,6434.94 h60
  text ".Layer_Name" at 577,-858.49 h60
M13 Component Bodies Top:
  text ".Layer_Name" at 577,-858.49 h60
M14 Component Bodies Bottom:
  text ".Layer_Name" at 577,-858.49 h60
M15 Courtyards Top:
  text ".Layer_Name" at 577,-858.49 h60
M16 Courtyards Bottom:
  text ".Layer_Name" at 577,-858.49 h60
Drill Drawing:
  circle w10: c5363.63,2421.26 r27.59
  lines w10: 5336.04,2517.84 5363.63,2531.64 5391.23,2517.84 5377.43,2545.44 5391.23,2573.03 5363.63,2559.24 5336.04,2573.03 5349.83,2545.44 5336.04,2517.84 ; 5336.04,2642.02 5391.23,2642.02 5391.23,2697.21 5336.04,2697.21 5336.04,2642.02 ; 5336.04,2779.99 5349.83,2779.99 5363.63,2766.2 5377.43,2779.99 5391.23,2779.99 5377.43,2793.79 5391.23,2807.59 5377.43,2807.59 5363.63,2821.39 5349.83,2807.59 5336.04,2807.59 5349.83,2793.79 5336.04,2779.99 ; 5336.04,2945.56 5391.23,2945.56 5363.63,2890.37 5336.04,2945.56 ; 5336.04,3014.55 5391.23,3014.55 5391.23,3069.74 5336.04,3069.74 5336.04,3014.55 ; 5336.04,3152.52 5349.83,3152.52 5349.83,3138.72 5377.43,3138.72 5377.43,3152.52 5391.23,3152.52 5391.23,3180.12 5377.43,3180.12 5377.43,3193.91 5349.83,3193.91 5349.83,3180.12 5336.04,3180.12 5336.04,3152.52 ; 5336.04,3262.9 5336.04,3276.7 5349.83,3290.5 5336.04,3304.29 5336.04,3318.09 5349.83,3318.09 5363.63,3304.29 5377.43,3318.09 5391.23,3318.09 5391.23,3304.29 5377.43,3290.5 5391.23,3276.7 5391.23,3262.9 5377.43,3262.9 5363.63,3276.7 5349.83,3262.9 5336.04,3262.9 ; 5347.07,3025.59 5380.19,3025.59 5380.19,3058.7 5347.07,3058.7 5347.07,3025.59
  lines w12: 5286,2356.42 8516.52,2356.42 ; 5286,3349.82 8516.52,3349.82 ; 5623.86,2232.24 5623.86,3474 ; 5955.86,2232.24 5955.86,3474 ; 6592.42,2232.24 6592.42,3474 ; 6851.53,2232.24 6851.53,3474 ; 7226.68,2232.24 7226.68,3474 ; 7950.06,2232.24 7950.06,3474 ; 5286,2232.24 8516.52,2232.24 8516.52,3474 5286,3474 5286,2232.24
  text "Symbol" at 5360.51,3387.08 h72
  text "Quantity" at 5661.11,3387.08 h72
  text "Finished Hole Size" at 5993.12,3387.08 h72
  text "Plated" at 6629.67,3387.08 h72
  text "Hole Type" at 6888.78,3387.08 h72
  text "Drill Layer Pair" at 7263.93,3387.08 h72
  text "Hole Tolerance" at 7987.32,3387.08 h72
  text "21" at 5661.11,3262.9 h60
  text "8.00mil (0.203mm)" at 5993.12,3262.9 h60
  text "PTH" at 6629.67,3262.9 h60
  text "Round" at 6888.78,3262.9 h60
  text "Top Layer - Bottom Layer" at 7263.93,3262.9 h60
  text "314" at 5661.11,3138.72 h60
  text "10.00mil (0.254mm)" at 5993.12,3138.72 h60
  text "PTH" at 6629.67,3138.72 h60
  text "Round" at 6888.78,3138.72 h60
  text "Top Layer - Bottom Layer" at 7263.93,3138.72 h60
  text "4" at 5661.11,3014.55 h60
  text "40.00mil (1.016mm)" at 5993.12,3014.55 h60
  text "PTH" at 6629.67,3014.55 h60
  text "Round" at 6888.78,3014.55 h60
  text "Top Layer - Bottom Layer" at 7263.93,3014.55 h60
  text "2" at 5661.11,2890.37 h60
  text "45.28mil (1.150mm)" at 5993.12,2890.37 h60
  text "PTH" at 6629.67,2890.37 h60
  text "Round" at 6888.78,2890.37 h60
  text "Top Layer - Bottom Layer" at 7263.93,2890.37 h60
  text "2" at 5661.11,2766.2 h60
  text "51.18mil (1.300mm)" at 5993.12,2766.2 h60
  text "PTH" at 6629.67,2766.2 h60
  text "Round" at 6888.78,2766.2 h60
  text "Top Layer - Bottom Layer" at 7263.93,2766.2 h60
  text "1" at 5661.11,2642.02 h60
  text "52.00mil (1.321mm)" at 5993.12,2642.02 h60
  text "PTH" at 6629.67,2642.02 h60
  text "Round" at 6888.78,2642.02 h60
  text "Top Layer - Bottom Layer" at 7263.93,2642.02 h60
  text "2" at 5661.11,2517.84 h60
  text "98.43mil (2.500mm)" at 5993.12,2517.84 h60
  text "PTH" at 6629.67,2517.84 h60
  text "Round" at 6888.78,2517.84 h60
  text "Top Layer - Bottom Layer" at 7263.93,2517.84 h60
  text "4" at 5661.11,2393.67 h60
  text "125.98mil (3.200mm)" at 5993.12,2393.67 h60
  text "PTH" at 6629.67,2393.67 h60
  text "Round" at 6888.78,2393.67 h60
  text "Top Layer - Bottom Layer" at 7263.93,2393.67 h60
  text "350 Total" at 5661.11,2269.49 h60
  text ".Layer_Name" at 577,-858.49 h60
M17 Embedded Cavity:
  text ".Layer_Name" at 577,-858.49 h60
M18 Embedded Assembly:
  text ".Layer_Name" at 577,-858.49 h60
M19 Embedded Keepout:
  text ".Layer_Name" at 577,-858.49 h60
